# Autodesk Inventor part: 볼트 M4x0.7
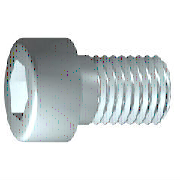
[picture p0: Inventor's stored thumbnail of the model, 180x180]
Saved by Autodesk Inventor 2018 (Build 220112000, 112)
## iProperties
IsCustomPart: 1
Created: 2015-10
Part Number: 볼트 M4x0.7
Material: 스테인리스강
Description: 6각머리 태핑 나사
Document SubType Name: Modeling
Standard: KS B 1003
Designer: mdu
Standards Organization: KS
Language: ko-KR
Size Designation: M 4 x 16
Categories: <MemberInstance><Categories><Category DisplayName="조임쇠" InternalName="e4da775c-781d-43d5-af7c-5136215cf5a6" Mnemonic="FSTN"><Category DisplayName="볼트" InternalN
Density: 8.08 g/cm^3
Mass: 2.70334 g
Surface Area: 3.81118 cm^2
Volume: 0.334572 cm^3
Appearance: 반광택
Author: mdu
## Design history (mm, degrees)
sketch "스케치1"
  geometry: L1 (-1, 0)-(16, 0); L2 (16, 0)-(16, 2); L3 (16, 2)-(1.75, 2); L4 (1.75, 2)-(1.32, 2); L5 (1.32, 2)-(0, 2); L6 (0, 2)-(0, 3.5); L7 (0, 3.5)-(-4, 3.5); L8 (-4, 3.5)-(-4, 1.732); L9 (-4, 1.732)-(-2, 1.732); L10 (-2, 1.732)-(-1, 0); L11 (-8, 0)-(20, 0) reference; L12 (0, -0.7)-(0, 4.2) reference; L13 (1.75, 2)-(0, 2)
  constraints: 22 end point, 6 parallel, 2 collinear, 2 perpendicular, 1 horizontal, 1 point on line
  dimensions: "d1" = 14.25 distance from line of L3.end L2 (= GEL); "d2" = 0.42952 distance of L4.end L3.end (computed from GAL); "d3" = 4 distance between parallel lines of L8 L6 (= KOH); "d4" = 2 distance of L8.end L9.end (= INTI); "d5" = 60 deg angle of L10 L1; "d6" = 4 diameter of L3 L1 (= GD); "d7" = 4 diameter of L5 L1 (= BDM); "d8" = 3.4641 diameter of L9 L1 (= 1.1547 x SW); "d9" = 7 diameter of L7 L1 (= KOD); "d26" = 16 distance between parallel lines of L12 L2 (= NLG)
revolve "본체" sketch "스케치1" stored, may be unused: angle "d10" = 90 deg
sketch "스케치2"
  geometry: L1 (0, -4.9)-(0, 4.9) reference; L2 (-4.9, 0)-(4.9, 0) reference; L3 (1.732, 0)-(0.866, -1.5); L4 (0.866, -1.5)-(-0.866, -1.5); L5 (-0.866, -1.5)-(-1.732, 0); L6 (-1.732, 0)-(-0.866, 1.5); L7 (-0.866, 1.5)-(0.866, 1.5); L8 (0.866, 1.5)-(1.732, 0); 2 further points
  constraints: 12 end point, 1 coincident, 1 horizontal alignment, 1 point on line, 12 other
extrude "슬롯" join sketch "스케치2" stored distance "d11" = 10; taper "d12" = 0 deg
workplane "Work Plane1"
fillet "Fillet2" dims "d30" = 0.1 (= R)
body "Solid1"
fillet "모깎기1" dims "d17" = 0.4 (= RR)
feature "스레드" dims "d13" = 14.25 (= GEL), "d14" = 0
chamfer "모따기1" distance "d15" = 0.42941 (= -0.5 x SPD + 0.5 x GD); stored, may be unused: second distance "d16" = 0.42941 (= GUL), angle "d27" = 45 deg
other parameters: "GD" = 4 (= NND) [user parameter; used in 2 equation terms], "NLG" = 16 [user parameter; used in 1 equation term], "GEL" = 14.25 [user parameter; used in 2 equation terms], "KOD" = 7 [user parameter; used in 1 equation term], "KOH" = 4 [user parameter; used in 1 equation term], "INTI" = 2 [user parameter; used in 1 equation term], "GAL" = 0.42941 (= 0.61345 x PTC) [user parameter; used in 1 equation term], "GUL" = 0.42941 (= 0.61345 x PTC) [user parameter; used in 1 equation term], "BDM" = 4 (= NND) [user parameter; used in 1 equation term], "SW" = 3 [user parameter; used in 2 equation terms], "RR" = 0.4 [user parameter; used in 1 equation term], "SPD" = 3.14117 (= NND - 1.2269 x PTC) [user parameter; used in 1 equation term], "d19" = 0, "d28" = 0, "d29" = 0, "R" = 0.1 [user parameter; used in 1 equation term], "PHH" = 0.2 [user parameter], "GD1" = 3.14117 (= THREADDIA - 1.2269 x PTC) [user parameter], "THREADDIA" = 4 [user parameter; used in 1 equation term], "FAWI" = 45 deg [user parameter], "TPU" = 14.28571 (computed from PTC) [user parameter], "PTC" = 0.7 [user parameter; used in 5 equation terms], "NND" = 4 [user parameter; used in 3 equation terms], "TOA" = 30 deg [user parameter], "E0" = 3.465 (= 1.155 x SW) [user parameter]
